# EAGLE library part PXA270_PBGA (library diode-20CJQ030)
Intel® PXA270 Processor PXA270 with PBGA package 23x23 Features: High-performance processor: -Intel XScale® microarchitecture with Intel® Wireless MMX? Technology -7 Stage pipeline -32 KB instruction cache -32 KB data cache -2 KB "mini" data cache -Extensive data buffering 256 Kbytes of internal SRAM for high speed code or data storage preserved during low-power states High-speed baseband processor interface (Mobile Scalable Link) Rich serial peripheral set: -AC?97 audio port -I2S audio port -USB Client controller -USB Host controller -USB On-The-Go controller -Three high-speed UARTs (two with hardware flow control) -FIR and SIR infrared communications port Hardware debug features ? IEEE JTAG interface with boundary scan Hardware performance-monitoring features with on-chip trace buffer Real-time clock Operating-system timers LCD Controller Universal Subscriber Identity Module interface Low power: -Wireless Intel Speedstep® Technology -Less than 500 mW typical internal dissipation -Supply voltage may be reduced to 0.85 V -Four low-power modes -Dynamic voltage and frequencymanagement High-performance memory controller: -Four banks of SDRAM: up to 104 MHz @ 2.5V, 3.0V, and 3.3V I/O interface -Six static chip selects -Support for PCMCIA and Compact Flash -Companion chip interface Flexible clocking: -CPU clock from 104 to 624 MHz -Flexible memory clock ratios -Frequency changes -Functional clock gating Additional peripherals for system connectivity: -SD Card / MMC Controller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
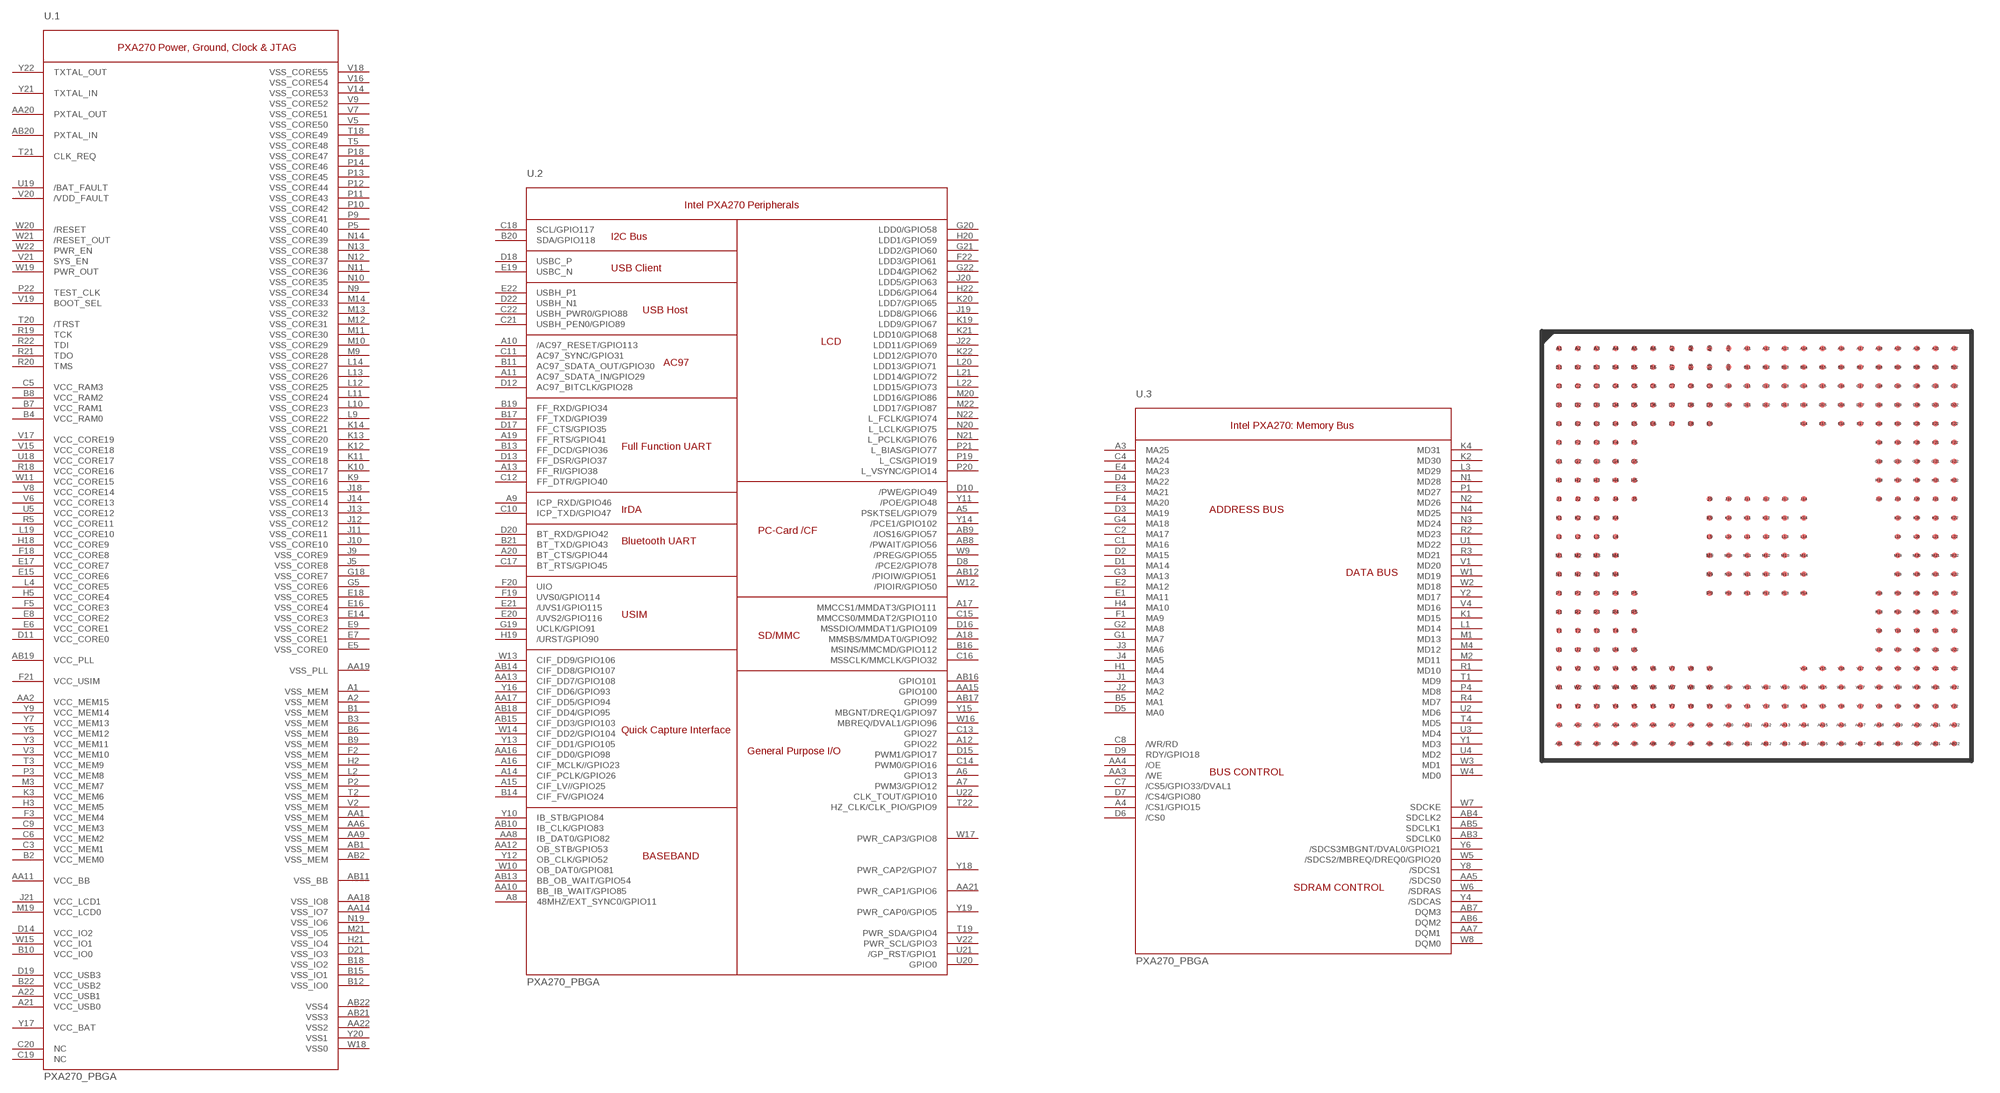
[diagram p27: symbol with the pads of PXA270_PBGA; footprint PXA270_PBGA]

Designator prefix U; gates .2=PXA270_PERIPHERALS .3=PXA_270_MEM_BUS .1=PXA270_PWR_CLK_23X23

## PXA270_PBGA  [PXA270_PBGA]
A1  .1:VSS_MEM
A2  .1:VSS_MEM
A3  .3:MA25  out
A4  .3:/CS1/GPIO15
A5  .2:PSKTSEL/GPIO79
A6  .2:GPIO13
A7  .2:PWM3/GPIO12
A8  .2:48MHZ/EXT_SYNC0/GPIO11
A9  .2:ICP_RXD/GPIO46
A10  .2:/AC97_RESET/GPIO113
A11  .2:AC97_SDATA_IN/GPIO29
A12  .2:GPIO22
A13  .2:FF_RI/GPIO38
A14  .2:CIF_PCLK/GPIO26
A15  .2:CIF_LV//GPIO25
A16  .2:CIF_MCLK//GPIO23
A17  .2:MMCCS1/MMDAT3/GPIO111
A18  .2:MMSBS/MMDAT0/GPIO92
A19  .2:FF_RTS/GPIO41
A20  .2:BT_CTS/GPIO44
A21  .1:VCC_USB0
A22  .1:VCC_USB1
AA1  .1:VSS_MEM
AA2  .1:VCC_MEM15
AA3  .3:/WE  out
AA4  .3:/OE  out
AA5  .3:/SDCS0  out
AA6  .1:VSS_MEM
AA7  .3:DQM1  out
AA8  .2:IB_DAT0/GPIO82
AA9  .1:VSS_MEM
AA10  .2:BB_IB_WAIT/GPIO85
AA11  .1:VCC_BB
AA12  .2:OB_STB/GPIO53
AA13  .2:CIF_DD7/GPIO108
AA14  .1:VSS_IO7
AA15  .2:GPIO100
AA16  .2:CIF_DD0/GPIO98
AA17  .2:CIF_DD5/GPIO94
AA18  .1:VSS_IO8
AA19  .1:VSS_PLL
AA20  .1:PXTAL_OUT
AA21  .2:PWR_CAP1/GPIO6
AA22  .1:VSS2
AB1  .1:VSS_MEM
AB2  .1:VSS_MEM
AB3  .3:SDCLK0  out
AB4  .3:SDCLK2  out
AB5  .3:SDCLK1  out
AB6  .3:DQM2  out
AB7  .3:DQM3  out
AB8  .2:/PWAIT/GPIO56
AB9  .2:/IOS16/GPIO57
AB10  .2:IB_CLK/GPIO83
AB11  .1:VSS_BB
AB12  .2:/PIOIW/GPIO51
AB13  .2:BB_OB_WAIT/GPIO54
AB14  .2:CIF_DD8/GPIO107
AB15  .2:CIF_DD3/GPIO103
AB16  .2:GPIO101
AB17  .2:GPIO99
AB18  .2:CIF_DD4/GPIO95
AB19  .1:VCC_PLL
AB20  .1:PXTAL_IN
AB21  .1:VSS3
AB22  .1:VSS4
B1  .1:VSS_MEM
B2  .1:VCC_MEM0
B3  .1:VSS_MEM
B4  .1:VCC_RAM0
B5  .3:MA1  out
B6  .1:VSS_MEM
B7  .1:VCC_RAM1
B8  .1:VCC_RAM2
B9  .1:VSS_MEM
B10  .1:VCC_IO0
B11  .2:AC97_SDATA_OUT/GPIO30
B12  .1:VSS_IO0
B13  .2:FF_DCD/GPIO36
B14  .2:CIF_FV/GPIO24
B15  .1:VSS_IO1
B16  .2:MSINS/MMCMD/GPIO112
B17  .2:FF_TXD/GPIO39
B18  .1:VSS_IO2
B19  .2:FF_RXD/GPIO34
B20  .2:SDA/GPIO118
B21  .2:BT_TXD/GPIO43
B22  .1:VCC_USB2
C1  .3:MA16  out
C2  .3:MA17  out
C3  .1:VCC_MEM1
C4  .3:MA24  out
C5  .1:VCC_RAM3
C6  .1:VCC_MEM2
C7  .3:/CS5/GPIO33/DVAL1
C8  .3:/WR/RD  out
C9  .1:VCC_MEM3
C10  .2:ICP_TXD/GPIO47
C11  .2:AC97_SYNC/GPIO31
C12  .2:FF_DTR/GPIO40
C13  .2:GPIO27
C14  .2:PWM0/GPIO16
C15  .2:MMCCS0/MMDAT2/GPIO110
C16  .2:MSSCLK/MMCLK/GPIO32
C17  .2:BT_RTS/GPIO45
C18  .2:SCL/GPIO117
C19  .1:NC
C20  .1:NC
C21  .2:USBH_PEN0/GPIO89
C22  .2:USBH_PWR0/GPIO88
D1  .3:MA14  out
D2  .3:MA15  out
D3  .3:MA19  out
D4  .3:MA22  out
D5  .3:MA0  out
D6  .3:/CS0  out
D7  .3:/CS4/GPIO80
D8  .2:/PCE2/GPIO78
D9  .3:RDY/GPIO18
D10  .2:/PWE/GPIO49
D11  .1:VCC_CORE0
D12  .2:AC97_BITCLK/GPIO28
D13  .2:FF_DSR/GPIO37
D14  .1:VCC_IO2
D15  .2:PWM1/GPIO17
D16  .2:MSSDIO/MMDAT1/GPIO109
D17  .2:FF_CTS/GPIO35
D18  .2:USBC_P
D19  .1:VCC_USB3
D20  .2:BT_RXD/GPIO42
D21  .1:VSS_IO3
D22  .2:USBH_N1
E1  .3:MA11  out
E2  .3:MA12  out
E3  .3:MA21  out
E4  .3:MA23  out
E5  .1:VSS_CORE0
E6  .1:VCC_CORE1
E7  .1:VSS_CORE1
E8  .1:VCC_CORE2
E9  .1:VSS_CORE2
E14  .1:VSS_CORE3
E15  .1:VCC_CORE6
E16  .1:VSS_CORE4
E17  .1:VCC_CORE7
E18  .1:VSS_CORE5
E19  .2:USBC_N
E20  .2:/UVS2/GPIO116
E21  .2:/UVS1/GPIO115
E22  .2:USBH_P1
F1  .3:MA9  out
F2  .1:VSS_MEM
F3  .1:VCC_MEM4
F4  .3:MA20  out
F5  .1:VCC_CORE3
F18  .1:VCC_CORE8
F19  .2:UVS0/GPIO114
F20  .2:UIO
F21  .1:VCC_USIM
F22  .2:LDD3/GPIO61
G1  .3:MA7  out
G2  .3:MA8  out
G3  .3:MA13  out
G4  .3:MA18  out
G5  .1:VSS_CORE6
G18  .1:VSS_CORE7
G19  .2:UCLK/GPIO91
G20  .2:LDD0/GPIO58
G21  .2:LDD2/GPIO60
G22  .2:LDD4/GPIO62
H1  .3:MA4  out
H2  .1:VSS_MEM
H3  .1:VCC_MEM5
H4  .3:MA10  out
H5  .1:VCC_CORE4
H18  .1:VCC_CORE9
H19  .2:/URST/GPIO90
H20  .2:LDD1/GPIO59
H21  .1:VSS_IO4
H22  .2:LDD6/GPIO64
J1  .3:MA3  out
J2  .3:MA2  out
J3  .3:MA6  out
J4  .3:MA5  out
J5  .1:VSS_CORE8
J9  .1:VSS_CORE9
J10  .1:VSS_CORE10
J11  .1:VSS_CORE11
J12  .1:VSS_CORE12
J13  .1:VSS_CORE13
J14  .1:VSS_CORE14
J18  .1:VSS_CORE15
J19  .2:LDD8/GPIO66
J20  .2:LDD5/GPIO63
J21  .1:VCC_LCD1
J22  .2:LDD11/GPIO69
K1  .3:MD15
K2  .3:MD30
K3  .1:VCC_MEM6
K4  .3:MD31
K9  .1:VSS_CORE16
K10  .1:VSS_CORE17
K11  .1:VSS_CORE18
K12  .1:VSS_CORE19
K13  .1:VSS_CORE20
K14  .1:VSS_CORE21
K19  .2:LDD9/GPIO67
K20  .2:LDD7/GPIO65
K21  .2:LDD10/GPIO68
K22  .2:LDD12/GPIO70
L1  .3:MD14
L2  .1:VSS_MEM
L3  .3:MD29
L4  .1:VCC_CORE5
L9  .1:VSS_CORE22
L10  .1:VSS_CORE23
L11  .1:VSS_CORE24
L12  .1:VSS_CORE25
L13  .1:VSS_CORE26
L14  .1:VSS_CORE27
L19  .1:VCC_CORE10
L20  .2:LDD13/GPIO71
L21  .2:LDD14/GPIO72
L22  .2:LDD15/GPIO73
M1  .3:MD13
M2  .3:MD11
M3  .1:VCC_MEM7
M4  .3:MD12
M9  .1:VSS_CORE28
M10  .1:VSS_CORE29
M11  .1:VSS_CORE30
M12  .1:VSS_CORE31
M13  .1:VSS_CORE32
M14  .1:VSS_CORE33
M19  .1:VCC_LCD0
M20  .2:LDD16/GPIO86
M21  .1:VSS_IO5
M22  .2:LDD17/GPIO87
N1  .3:MD28
N2  .3:MD26
N3  .3:MD24
N4  .3:MD25
N9  .1:VSS_CORE34
N10  .1:VSS_CORE35
N11  .1:VSS_CORE36
N12  .1:VSS_CORE37
N13  .1:VSS_CORE38
N14  .1:VSS_CORE39
N19  .1:VSS_IO6
N20  .2:L_LCLK/GPIO75
N21  .2:L_PCLK/GPIO76
N22  .2:L_FCLK/GPIO74
P1  .3:MD27
P2  .1:VSS_MEM
P3  .1:VCC_MEM8
P4  .3:MD8
P5  .1:VSS_CORE40
P9  .1:VSS_CORE41
P10  .1:VSS_CORE42
P11  .1:VSS_CORE43
P12  .1:VSS_CORE44
P13  .1:VSS_CORE45
P14  .1:VSS_CORE46
P18  .1:VSS_CORE47
P19  .2:L_CS/GPIO19
P20  .2:L_VSYNC/GPIO14
P21  .2:L_BIAS/GPIO77
P22  .1:TEST_CLK
R1  .3:MD10
R2  .3:MD23
R3  .3:MD21
R4  .3:MD7
R5  .1:VCC_CORE11
R18  .1:VCC_CORE16
R19  .1:TCK
R20  .1:TMS
R21  .1:TDO
R22  .1:TDI
T1  .3:MD9
T2  .1:VSS_MEM
T3  .1:VCC_MEM9
T4  .3:MD5
T5  .1:VSS_CORE48
T18  .1:VSS_CORE49
T19  .2:PWR_SDA/GPIO4
T20  .1:/TRST
T21  .1:CLK_REQ
T22  .2:HZ_CLK/CLK_PIO/GPIO9
U1  .3:MD22
U2  .3:MD6
U3  .3:MD4
U4  .3:MD2
U5  .1:VCC_CORE12
U18  .1:VCC_CORE17
U19  .1:/BAT_FAULT
U20  .2:GPIO0
U21  .2:/GP_RST/GPIO1
U22  .2:CLK_TOUT/GPIO10
V1  .3:MD20
V2  .1:VSS_MEM
V3  .1:VCC_MEM10
V4  .3:MD16
V5  .1:VSS_CORE50
V6  .1:VCC_CORE13
V7  .1:VSS_CORE51
V8  .1:VCC_CORE14
V9  .1:VSS_CORE52
V14  .1:VSS_CORE53
V15  .1:VCC_CORE18
V16  .1:VSS_CORE54
V17  .1:VCC_CORE19
V18  .1:VSS_CORE55
V19  .1:BOOT_SEL
V20  .1:/VDD_FAULT
V21  .1:SYS_EN
V22  .2:PWR_SCL/GPIO3
W1  .3:MD19
W2  .3:MD18
W3  .3:MD1
W4  .3:MD0
W5  .3:/SDCS2/MBREQ/DREQ0/GPIO20
W6  .3:/SDRAS  out
W7  .3:SDCKE  out
W8  .3:DQM0  out
W9  .2:/PREG/GPIO55
W10  .2:OB_DAT0/GPIO81
W11  .1:VCC_CORE15
W12  .2:/PIOIR/GPIO50
W13  .2:CIF_DD9/GPIO106
W14  .2:CIF_DD2/GPIO104
W15  .1:VCC_IO1
W16  .2:MBREQ/DVAL1/GPIO96
W17  .2:PWR_CAP3/GPIO8
W18  .1:VSS0
W19  .1:PWR_OUT
W20  .1:/RESET
W21  .1:/RESET_OUT
W22  .1:PWR_EN
Y1  .3:MD3
Y2  .3:MD17
Y3  .1:VCC_MEM11
Y4  .3:/SDCAS  out
Y5  .1:VCC_MEM12
Y6  .3:/SDCS3MBGNT/DVAL0/GPIO21
Y7  .1:VCC_MEM13
Y8  .3:/SDCS1  out
Y9  .1:VCC_MEM14
Y10  .2:IB_STB/GPIO84
Y11  .2:/POE/GPIO48
Y12  .2:OB_CLK/GPIO52
Y13  .2:CIF_DD1/GPIO105
Y14  .2:/PCE1/GPIO102
Y15  .2:MBGNT/DREQ1/GPIO97
Y16  .2:CIF_DD6/GPIO93
Y17  .1:VCC_BAT
Y18  .2:PWR_CAP2/GPIO7
Y19  .2:PWR_CAP0/GPIO5
Y20  .1:VSS1
Y21  .1:TXTAL_IN
Y22  .1:TXTAL_OUT

## Footprint PXA270_PBGA (pad centres in mm)
23x23 mm PBGA Intel® PXA270 Processor Package 1mm pitch; 0.3 mm diameter Please send any comments to: messi@users.sourceforge.net
smd 0.3 x 0.3: A1 -10.5,10.5; A2 -9.5,10.5; A3 -8.5,10.5; A4 -7.5,10.5; A5 -6.5,10.5; A6 -5.5,10.5; A7 -4.5,10.5; A8 -3.5,10.5; A9 -2.5,10.5; A10 -1.5,10.5; A11 -0.5,10.5; A12 0.5,10.5; A13 1.5,10.5; A14 2.5,10.5; A15 3.5,10.5; A16 4.5,10.5; A17 5.5,10.5; A18 6.5,10.5; A19 7.5,10.5; A20 8.5,10.5; A21 9.5,10.5; A22 10.5,10.5; AA1 -10.5,-9.5; AA2 -9.5,-9.5; AA3 -8.5,-9.5; AA4 -7.5,-9.5; AA5 -6.5,-9.5; AA6 -5.5,-9.5; AA7 -4.5,-9.5; AA8 -3.5,-9.5; AA9 -2.5,-9.5; AA10 -1.5,-9.5; AA11 -0.5,-9.5; AA12 0.5,-9.5; AA13 1.5,-9.5; AA14 2.5,-9.5; AA15 3.5,-9.5; AA16 4.5,-9.5; AA17 5.5,-9.5; AA18 6.5,-9.5; AA19 7.5,-9.5; AA20 8.5,-9.5; AA21 9.5,-9.5; AA22 10.5,-9.5; AB1 -10.5,-10.5; AB2 -9.5,-10.5; AB3 -8.5,-10.5; AB4 -7.5,-10.5; AB5 -6.5,-10.5; AB6 -5.5,-10.5; AB7 -4.5,-10.5; AB8 -3.5,-10.5; AB9 -2.5,-10.5; AB10 -1.5,-10.5; AB11 -0.5,-10.5; AB12 0.5,-10.5; AB13 1.5,-10.5; AB14 2.5,-10.5; AB15 3.5,-10.5; AB16 4.5,-10.5; AB17 5.5,-10.5; AB18 6.5,-10.5; AB19 7.5,-10.5; AB20 8.5,-10.5; AB21 9.5,-10.5; AB22 10.5,-10.5; B1 -10.5,9.5; B2 -9.5,9.5; B3 -8.5,9.5; B4 -7.5,9.5; B5 -6.5,9.5; B6 -5.5,9.5; B7 -4.5,9.5; B8 -3.5,9.5; B9 -2.5,9.5; B10 -1.5,9.5; B11 -0.5,9.5; B12 0.5,9.5; B13 1.5,9.5; B14 2.5,9.5; B15 3.5,9.5; B16 4.5,9.5; B17 5.5,9.5; B18 6.5,9.5; B19 7.5,9.5; B20 8.5,9.5; B21 9.5,9.5; B22 10.5,9.5; C1 -10.5,8.5; C2 -9.5,8.5; C3 -8.5,8.5; C4 -7.5,8.5; C5 -6.5,8.5; C6 -5.5,8.5; C7 -4.5,8.5; C8 -3.5,8.5; C9 -2.5,8.5; C10 -1.5,8.5; C11 -0.5,8.5; C12 0.5,8.5; C13 1.5,8.5; C14 2.5,8.5; C15 3.5,8.5; C16 4.5,8.5; C17 5.5,8.5; C18 6.5,8.5; C19 7.5,8.5; C20 8.5,8.5; C21 9.5,8.5; C22 10.5,8.5; D1 -10.5,7.5; D2 -9.5,7.5; D3 -8.5,7.5; D4 -7.5,7.5; D5 -6.5,7.5; D6 -5.5,7.5; D7 -4.5,7.5; D8 -3.5,7.5; D9 -2.5,7.5; D10 -1.5,7.5; D11 -0.5,7.5; D12 0.5,7.5; D13 1.5,7.5; D14 2.5,7.5; D15 3.5,7.5; D16 4.5,7.5; D17 5.5,7.5; D18 6.5,7.5; D19 7.5,7.5; D20 8.5,7.5; D21 9.5,7.5; D22 10.5,7.5; E1 -10.5,6.5; E2 -9.5,6.5; E3 -8.5,6.5; E4 -7.5,6.5; E5 -6.5,6.5; E6 -5.5,6.5; E7 -4.5,6.5; E8 -3.5,6.5; E9 -2.5,6.5; E14 2.5,6.5; E15 3.5,6.5; E16 4.5,6.5; E17 5.5,6.5; E18 6.5,6.5; E19 7.5,6.5; E20 8.5,6.5; E21 9.5,6.5; E22 10.5,6.5; F1 -10.5,5.5; F2 -9.5,5.5; F3 -8.5,5.5; F4 -7.5,5.5; F5 -6.5,5.5; F18 6.5,5.5; F19 7.5,5.5; F20 8.5,5.5; F21 9.5,5.5; F22 10.5,5.5; G1 -10.5,4.5; G2 -9.5,4.5; G3 -8.5,4.5; G4 -7.5,4.5; G5 -6.5,4.5; G18 6.5,4.5; G19 7.5,4.5; G20 8.5,4.5; G21 9.5,4.5; G22 10.5,4.5; H1 -10.5,3.5; H2 -9.5,3.5; H3 -8.5,3.5; H4 -7.5,3.5; H5 -6.5,3.5; H18 6.5,3.5; H19 7.5,3.5; H20 8.5,3.5; H21 9.5,3.5; H22 10.5,3.5; J1 -10.5,2.5; J2 -9.5,2.5; J3 -8.5,2.5; J4 -7.5,2.5; J5 -6.5,2.5; J9 -2.5,2.5; J10 -1.5,2.5; J11 -0.5,2.5; J12 0.5,2.5; J13 1.5,2.5; J14 2.5,2.5; J18 6.5,2.5; J19 7.5,2.5; J20 8.5,2.5; J21 9.5,2.5; J22 10.5,2.5; K1 -10.5,1.5; K2 -9.5,1.5; K3 -8.5,1.5; K4 -7.5,1.5; K9 -2.5,1.5; K10 -1.5,1.5; K11 -0.5,1.5; K12 0.5,1.5; K13 1.5,1.5; K14 2.5,1.5; K19 7.5,1.5; K20 8.5,1.5; K21 9.5,1.5; K22 10.5,1.5; L1 -10.5,0.5; L2 -9.5,0.5; L3 -8.5,0.5; L4 -7.5,0.5; L9 -2.5,0.5; L10 -1.5,0.5; L11 -0.5,0.5; L12 0.5,0.5; L13 1.5,0.5; L14 2.5,0.5; L19 7.5,0.5; L20 8.5,0.5; L21 9.5,0.5; L22 10.5,0.5; M1 -10.5,-0.5; M2 -9.5,-0.5; M3 -8.5,-0.5; M4 -7.5,-0.5; M9 -2.5,-0.5; M10 -1.5,-0.5; M11 -0.5,-0.5; M12 0.5,-0.5; M13 1.5,-0.5; M14 2.5,-0.5; M19 7.5,-0.5; M20 8.5,-0.5; M21 9.5,-0.5; M22 10.5,-0.5; N1 -10.5,-1.5; N2 -9.5,-1.5; N3 -8.5,-1.5; N4 -7.5,-1.5; N9 -2.5,-1.5; N10 -1.5,-1.5; N11 -0.5,-1.5; N12 0.5,-1.5; N13 1.5,-1.5; N14 2.5,-1.5; N19 7.5,-1.5; N20 8.5,-1.5; N21 9.5,-1.5; N22 10.5,-1.5; P1 -10.5,-2.5; P2 -9.5,-2.5; P3 -8.5,-2.5; P4 -7.5,-2.5; P5 -6.5,-2.5; P9 -2.5,-2.5; P10 -1.5,-2.5; P11 -0.5,-2.5; P12 0.5,-2.5; P13 1.5,-2.5; P14 2.5,-2.5; P18 6.5,-2.5; P19 7.5,-2.5; P20 8.5,-2.5; P21 9.5,-2.5; P22 10.5,-2.5; R1 -10.5,-3.5; R2 -9.5,-3.5; R3 -8.5,-3.5; R4 -7.5,-3.5; R5 -6.5,-3.5; R18 6.5,-3.5; R19 7.5,-3.5; R20 8.5,-3.5; R21 9.5,-3.5; R22 10.5,-3.5; T1 -10.5,-4.5; T2 -9.5,-4.5; T3 -8.5,-4.5; T4 -7.5,-4.5; T5 -6.5,-4.5; T18 6.5,-4.5; T19 7.5,-4.5; T20 8.5,-4.5; T21 9.5,-4.5; T22 10.5,-4.5; U1 -10.5,-5.5; U2 -9.5,-5.5; U3 -8.5,-5.5; U4 -7.5,-5.5; U5 -6.5,-5.5; U18 6.5,-5.5; U19 7.5,-5.5; U20 8.5,-5.5; U21 9.5,-5.5; U22 10.5,-5.5; V1 -10.5,-6.5; V2 -9.5,-6.5; V3 -8.5,-6.5; V4 -7.5,-6.5; V5 -6.5,-6.5; V6 -5.5,-6.5; V7 -4.5,-6.5; V8 -3.5,-6.5; V9 -2.5,-6.5; V14 2.5,-6.5; V15 3.5,-6.5; V16 4.5,-6.5; V17 5.5,-6.5; V18 6.5,-6.5; V19 7.5,-6.5; V20 8.5,-6.5; V21 9.5,-6.5; V22 10.5,-6.5; W1 -10.5,-7.5; W2 -9.5,-7.5; W3 -8.5,-7.5; W4 -7.5,-7.5; W5 -6.5,-7.5; W6 -5.5,-7.5; W7 -4.5,-7.5; W8 -3.5,-7.5; W9 -2.5,-7.5; W10 -1.5,-7.5; W11 -0.5,-7.5; W12 0.5,-7.5; W13 1.5,-7.5; W14 2.5,-7.5; W15 3.5,-7.5; W16 4.5,-7.5; W17 5.5,-7.5; W18 6.5,-7.5; W19 7.5,-7.5; W20 8.5,-7.5; W21 9.5,-7.5; W22 10.5,-7.5; Y1 -10.5,-8.5; Y2 -9.5,-8.5; Y3 -8.5,-8.5; Y4 -7.5,-8.5; Y5 -6.5,-8.5; Y6 -5.5,-8.5; Y7 -4.5,-8.5; Y8 -3.5,-8.5; Y9 -2.5,-8.5; Y10 -1.5,-8.5; Y11 -0.5,-8.5; Y12 0.5,-8.5; Y13 1.5,-8.5; Y14 2.5,-8.5; Y15 3.5,-8.5; Y16 4.5,-8.5; Y17 5.5,-8.5; Y18 6.5,-8.5; Y19 7.5,-8.5; Y20 8.5,-8.5; Y21 9.5,-8.5; Y22 10.5,-8.5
